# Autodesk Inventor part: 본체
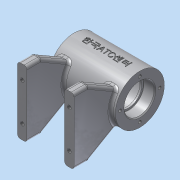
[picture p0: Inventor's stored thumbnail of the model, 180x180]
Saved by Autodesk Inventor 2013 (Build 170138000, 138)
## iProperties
Created: 2018-05
Part Number: 본체
Material: 알루미늄 6061
Document SubType Name: Modeling
Designer: dgall
Density: 2.71 g/cm^3
Mass: 319.021 g
Surface Area: 375.652 cm^2
Volume: 117.72 cm^3
Author: dgall
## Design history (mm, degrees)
sketch "스케치1"
  geometry: L1 (0, 0)-(70, 0); L2 (0, 16)-(0, 26); L3 (0, 26)-(70, 26); L4 (70, 26)-(70, 16); L5 (0, 16)-(12, 16); L6 (12, 16)-(12, 14); L7 (12, 14)-(14, 14); L8 (14, 14)-(14, 21); L9 (14, 21)-(56, 21); L10 (56, 21)-(56, 14); L11 (56, 14)-(58, 14); L12 (58, 14)-(58, 16); L13 (58, 16)-(70, 16)
  constraints: 26 end point, 6 perpendicular, 4 parallel, 2 collinear, 2 horizontal, 2 horizontal alignment, 2 vertical alignment, 1 vertical
  dimensions: "d0" = 70 distance of L1.start L1.end; "d1" = 52 diameter of L3 L1; "d2" = 12 distance of L2.start L5.end; "d3" = 42 distance of L8.end L9.end; "d4" = 32 diameter of L5 L1; "d5" = 28 diameter of L7 L1; "d6" = 42 diameter of L9 L1
revolve "회전1" sketch "스케치1" stored, may be unused: angle "d7" = 90 deg
sketch "스케치2"
  geometry: C1 r 26 at (0, 0) reference; 1 further point
  constraints: 1 vertical alignment
  dimensions: "d8" = 21 distance of C1.centre point (0, 21)
hole "구멍1" sketch "스케치2" at (0, 21) diameter "d9" = 3.242; stored, may be unused: countersink angle "d13" = 90 deg, drill point angle "d15" = 118 deg; dims "d10" = 8, "d11" = 4, "d12" = 2, "d14" = 10
node "작업 평면1"
node "작업 평면3"
  node "작업 평면2"
sketch "스케치3"
  geometry: L1 (0, 26)-(0, -26) reference; C1 r 5 at (-35, 0); 2 further points
  constraints: 1 centre point, 1 horizontal alignment, 1 midpoint
  dimensions: "d20" = 35 distance from line of L1 C1.centre; "d21" = 10 diameter of C1
extrude "돌출1" join sketch "스케치3" stored distance "d22" = 10; taper "d23" = 0 deg
sketch "스케치4"
  geometry: C1 r 5 at (0, 0) reference; 2 further points
  constraints: 1 coincident
hole "구멍2" sketch "스케치4" at (0, 0) diameter "d25" = 5.188; stored, may be unused: countersink angle "d29" = 90 deg, drill point angle "d31" = 118 deg; dims "d26" = 8, "d27" = 4, "d28" = 2, "d30" = 10
node "작업 평면5"
  node "작업 평면4"
sketch "스케치5"
  geometry: L1 (-17.325, -19.386)-(-35, -50); L2 (-35, -50)-(-35, -65); L3 (-35, -65)-(35, -65); L4 (35, -65)-(35, -50); L5 (35, -50)-(17.325, -19.386); C1 r 1.621 at (-21, 0) reference; C2 r 1.621 at (0, -21) reference; C3 r 1.621 at (21, 0) reference; C4 r 1.621 at (0, 21) reference; C5 r 16 at (0, 0) reference; A1 r 26 centre (0, 0) between (-17.325, -19.386) and (17.325, -19.386) reference; 2 further points
  constraints: 10 end point, 2 perpendicular, 2 point on circle, 1 equal length, 1 midpoint, 1 vertical, 1 vertical alignment
  dimensions: "d33" = 30 deg angle of L5 L4; "d34" = 70 distance of L2.end L3.end; "d36" = 15 distance of L3.end L4.end; "d37" = 65 distance from line of point (0, 0) L3; "d38" = 30 deg angle of L1 L2
extrude "돌출2" join sketch "스케치5" distance "d39" = 10; taper "d40" = 0 deg
sketch "스케치6"
  geometry: L1 (0, 0)-(0, -43.641); L2 (0, 0)-(0, -43.641); L3 (0, 0)-(-9.919, -27.251); C1 r 1.621 at (-21, 0) reference; C2 r 1.621 at (0, -21) reference; C3 r 1.621 at (21, 0) reference; C4 r 1.621 at (0, 21) reference; C5 r 26 at (0, 0) reference; C6 r 16 at (0, 0) reference; 1 further point
  constraints: 6 end point, 1 collinear, 1 vertical
  dimensions: "d80" = 20 deg angle of L1 L3; "d81" = 29 distance of L1.start L3.end
  node "투영된 루프2"
node "작업 평면12"
sketch "스케치12"
  geometry: C1 r 6 at (0, 0); 2 further points
  constraints: 1 centre point, 1 coincident
  dimensions: "d82" = 12 diameter of C1
extrude "돌출4" join sketch "스케치12" stored distance "d84" = 10; taper "d85" = 0 deg
sketch "스케치13"
  geometry: C1 r 6 at (0, 0) reference; 2 further points
  constraints: 1 coincident
hole "구멍5" sketch "스케치13" at (0, 0) diameter "d86" = 5.188; stored, may be unused: countersink angle "d90" = 90 deg, drill point angle "d92" = 118 deg; dims "d87" = 8, "d88" = 4, "d89" = 2, "d91" = 10
fillet "모깎기7" dims "d93" = 2
sketch "스케치9"
  geometry: L1 (0, 70)-(-10, 70) reference; 4 further points
  constraints: 2 vertical alignment, 1 midpoint
  dimensions: "d54" = 20 vertical distance of point (-15, 35) point (-5, 55); "d55" = 20 vertical distance of point (-15, 35) point (-5, 15)
hole "구멍4" sketch "스케치9" at (-5, 55), (-5, 15) diameter "d56" = 4.134; stored, may be unused: countersink angle "d60" = 90 deg, drill point angle "d62" = 118 deg; dims "d57" = 8, "d58" = 4, "d59" = 2, "d61" = 10
node "작업 평면7"
chamfer "모따기1" distance "d63" = 1; stored, may be unused: second distance "d64" = 2, angle "d65" = 45 deg
fillet "모깎기1" dims "d66" = 3
fillet "모깎기2" dims "d67" = 0.3
fillet "모깎기3" dims "d68" = 2
fillet "모깎기5" dims "d70" = 3
fillet "모깎기6" dims "d71" = 3
node "작업 평면14"
  node "작업 평면13"
sketch "스케치14"
  geometry: L1 (0, -26)-(0, 26) reference; 2 further points
  constraints: 1 horizontal alignment, 1 other
  dimensions: "d95" = 35 distance from line of L1 point (35, 0)
feature "엠보싱3" sketch "스케치14" dims "d0" = 70, "d1" = 52, "d2" = 12, "d3" = 42, "d4" = 32, "d5" = 28, "d6" = 42, "d96" = 0.5, "d97" = 0
node "솔리드1"
pattern_circular "원형 패턴1" dims angle "d17" = 360 deg
mirror "대칭1"
mirror "대칭2"
mirror "대칭3"
node "투영된 루프1"
other parameters: "d24" = 29, "d94" = 101
